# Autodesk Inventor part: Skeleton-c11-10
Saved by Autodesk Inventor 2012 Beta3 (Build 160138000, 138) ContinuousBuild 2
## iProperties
Created: 2011-01
Part Number: Skeleton-c11-10
Material: Default
Document SubType Name: Modeling
Designer: Beta-8540w
Density: 1 g/cm^3
_SkeletonDoc: Frame Skeleton File
_Version: 15.0.0
Author: Beta-8540w
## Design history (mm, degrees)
sketch "Reference Skeleton"
  geometry: L1 through (404.523, 1164.395) direction (1, 0); L2 through (325.691, 1070.446) direction (1, 0); 34 other entities
  constraints: 10 horizontal
